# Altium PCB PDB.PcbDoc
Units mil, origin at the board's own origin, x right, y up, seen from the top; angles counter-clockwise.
Board outline 4440 x 3165 mil, 2 copper layers (Top Layer, Bottom Layer); 19 components, 6 nets, 44 pads, 729 vias.
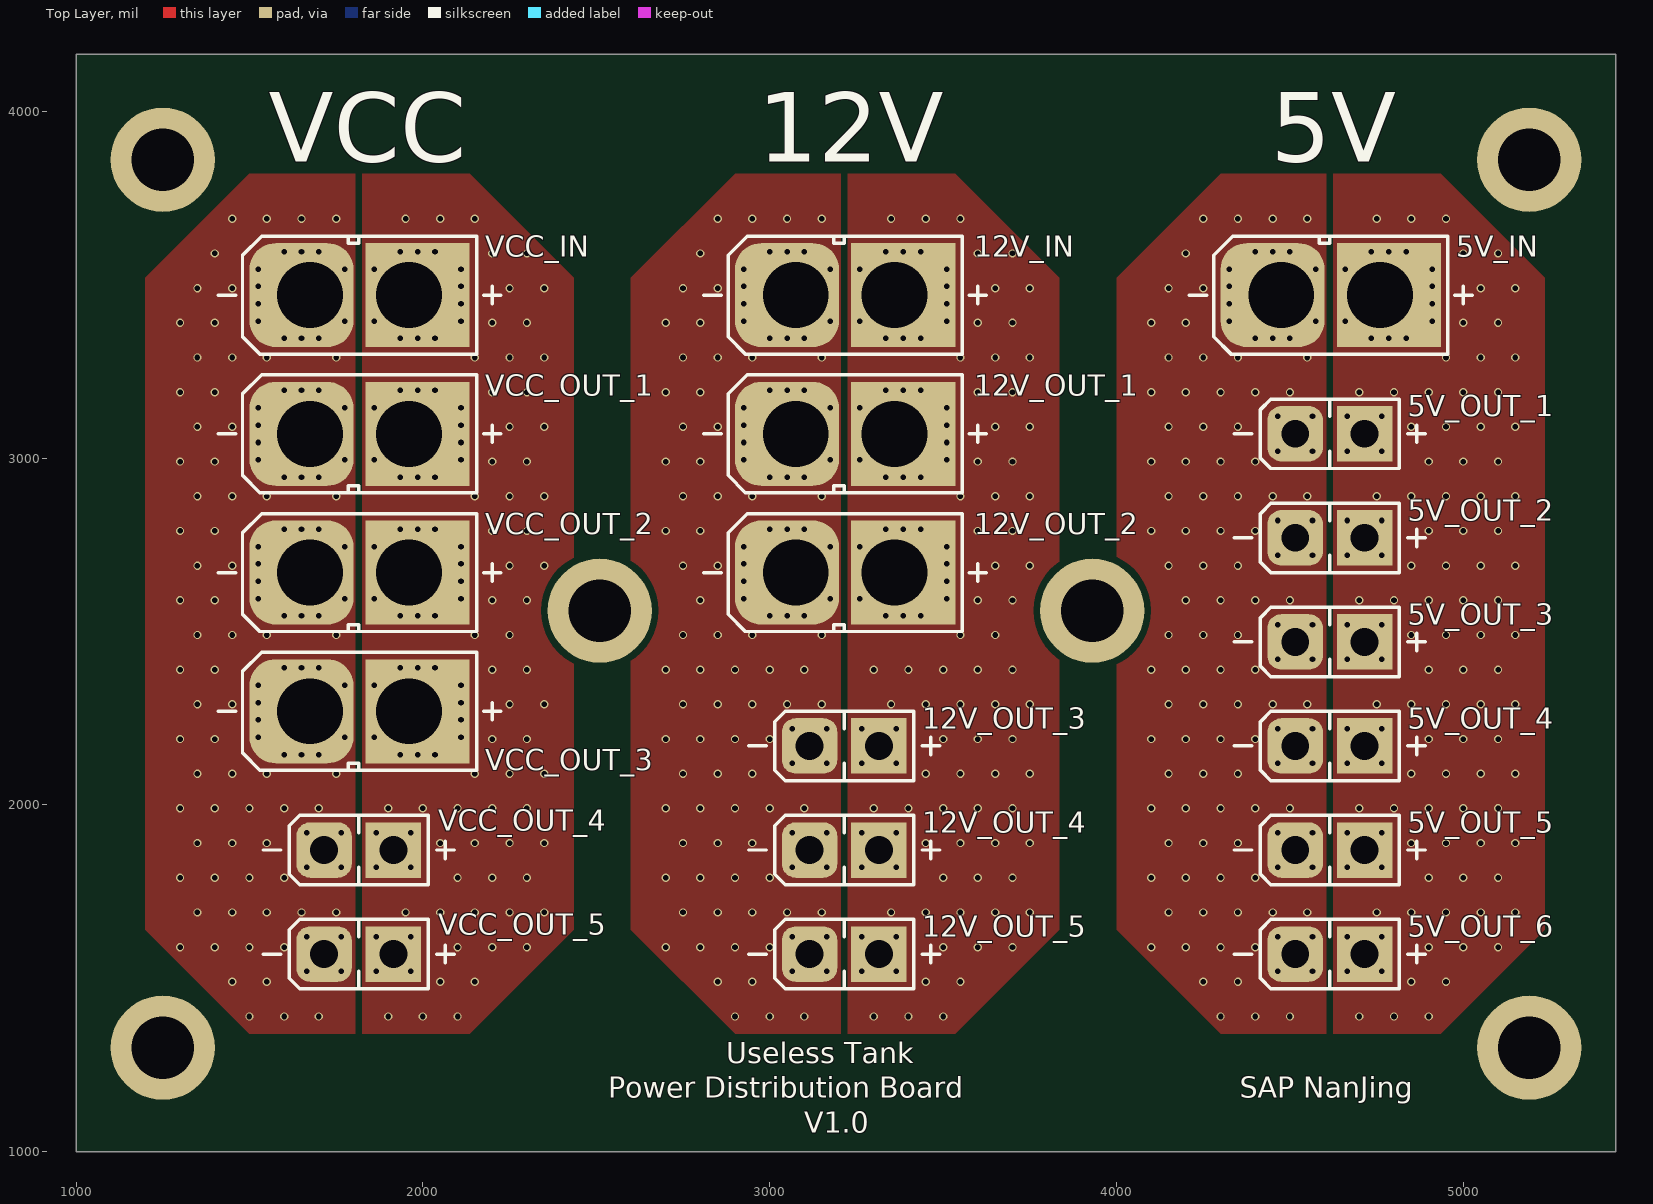
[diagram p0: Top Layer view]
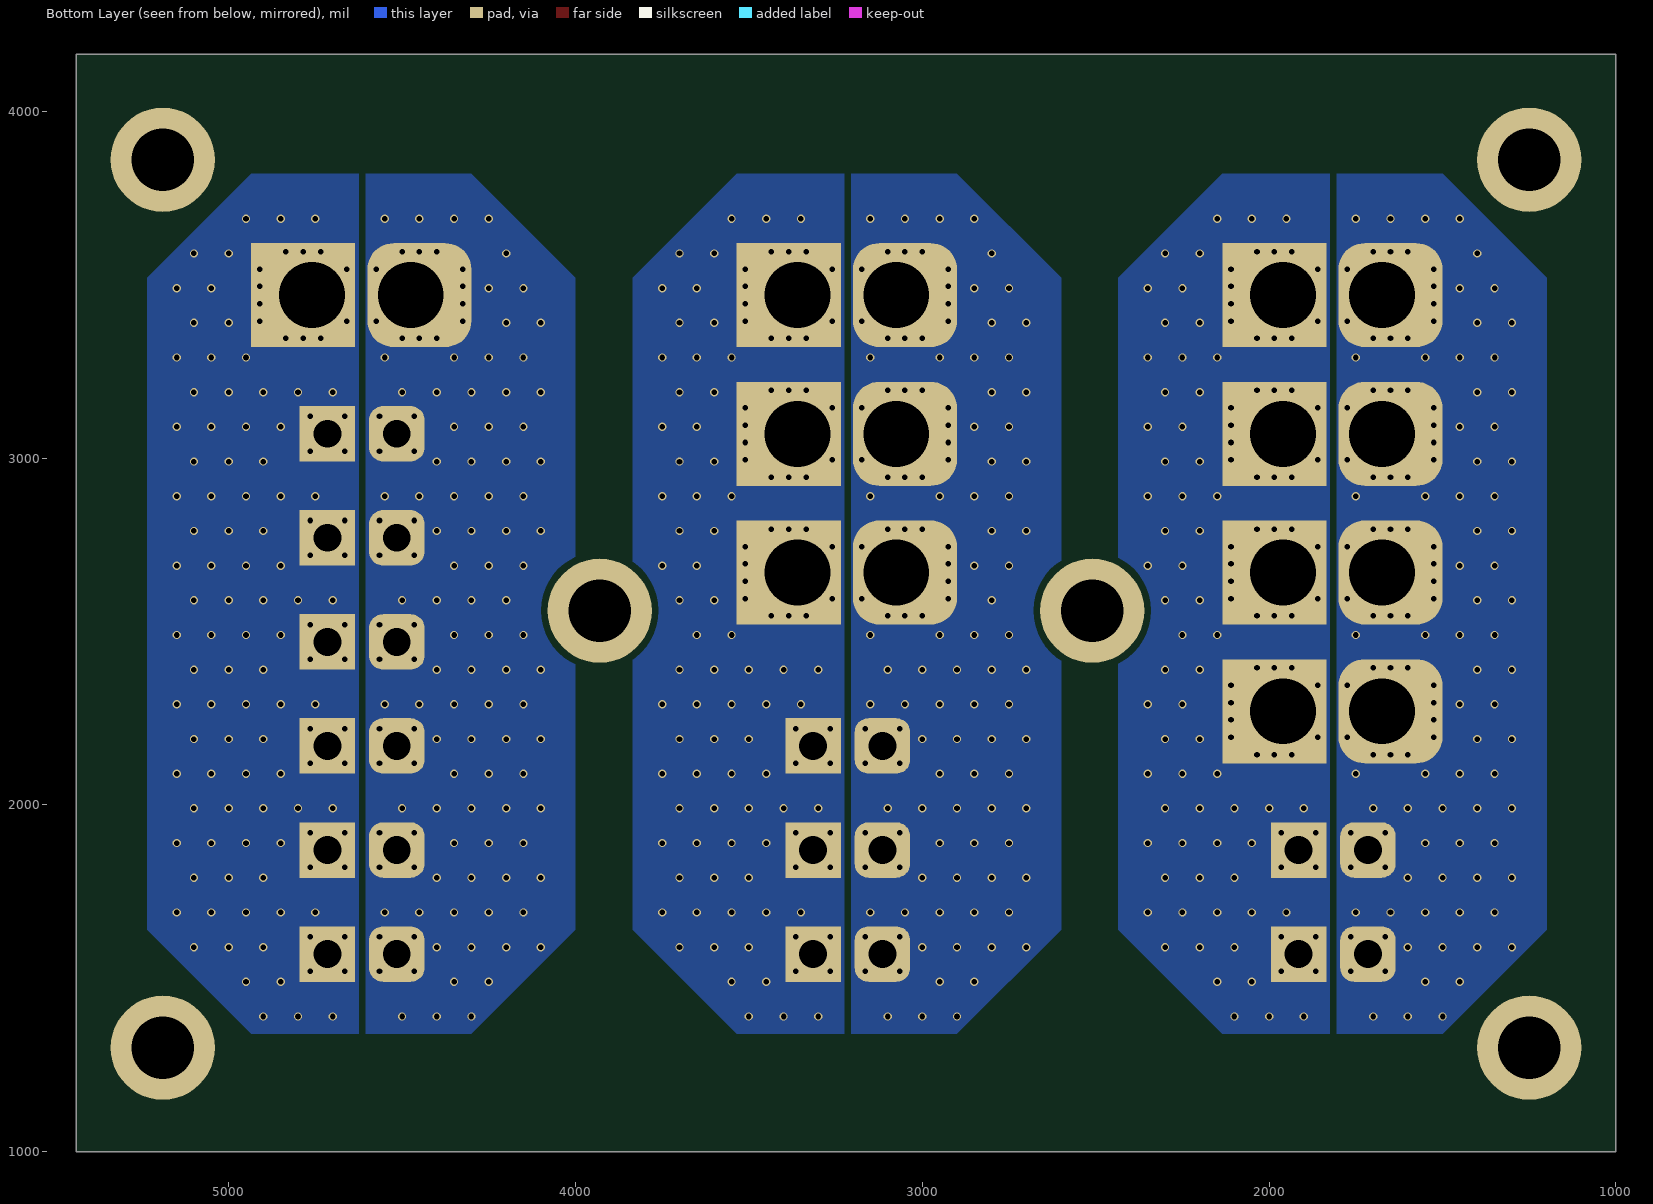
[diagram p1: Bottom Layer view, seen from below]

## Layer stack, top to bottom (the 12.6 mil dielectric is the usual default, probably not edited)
Top Solder: solder mask 0.4, Solder Resist, Dk 3.5
Top Layer: signal copper 1.4
Dielectric 1: dielectric 12.6, FR-4, Dk 4.8
Bottom Layer: signal copper 1.4
Bottom Solder: solder mask 0.4, Solder Resist, Dk 3.5

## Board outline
1000,1000 1000,4165 5440,4165 5440,1000

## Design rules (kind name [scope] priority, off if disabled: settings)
Clearance [All] p1: gap=20
HoleSize [All] p1: absolutevalues=TRUE maxlimit=200 minlimit=12 maxpercent=80.000 minpercent=20.000
PolygonConnect "Full Connect" [All] p1: connectstyle=Direct reliefconductorwidth=10 reliefentries=4 polygonreliefangle="90 Angle" airgapwidth=10
PolygonConnect [All] p2: connectstyle=Relief reliefconductorwidth=10 reliefentries=4 polygonreliefangle="90 Angle" airgapwidth=10
RoutingVias [All] p1: holewidth=16 width=24 viastyle="Through Hole" minholewidth=8 minwidth=14 maxholewidth=50 maxwidth=80
SolderMaskExpansion [All] p1: expansion=4
Width [All] p1: maxlimit=10 minlimit=8 preferedwidth=10
29 further rules are at their usual default settings.

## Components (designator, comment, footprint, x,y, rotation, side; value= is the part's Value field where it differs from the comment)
5V_IN "Header XT30/60/90" XT60PB-M 4475,3470 r0 top
5V_OUT_1 "Header XT30/60/90" XT30UPB-F 4515,3070 r0 top
5V_OUT_2 "Header XT30/60/90" XT30UPB-F 4515,2770 r0 top
5V_OUT_3 "Header XT30/60/90" XT30UPB-F 4515,2470 r0 top
5V_OUT_4 "Header XT30/60/90" XT30UPB-F 4515,2170 r0 top
5V_OUT_5 "Header XT30/60/90" XT30UPB-F 4515,1870 r0 top
5V_OUT_6 "Header XT30/60/90" XT30UPB-F 4515,1570 r0 top
12V_IN "Header XT30/60/90" XT60PB-M 3075,3470 r0 top
12V_OUT_1 "Header XT30/60/90" XT60PB-F 3075,3070 r0 top
12V_OUT_2 "Header XT30/60/90" XT60PB-F 3075,2670 r0 top
12V_OUT_3 "Header XT30/60/90" XT30UPB-F 3115,2170 r0 top
12V_OUT_4 "Header XT30/60/90" XT30UPB-F 3115,1870 r0 top
12V_OUT_5 "Header XT30/60/90" XT30UPB-F 3115,1570 r0 top
VCC_IN "Header XT30/60/90" XT60PB-M 1675,3470 r0 top
VCC_OUT_1 "Header XT30/60/90" XT60PB-F 1675,3070 r0 top
VCC_OUT_2 "Header XT30/60/90" XT60PB-F 1675,2670 r0 top
VCC_OUT_3 "Header XT30/60/90" XT60PB-F 1675,2270 r0 top
VCC_OUT_4 "Header XT30/60/90" XT30UPB-F 1715,1870 r0 top
VCC_OUT_5 "Header XT30/60/90" XT30UPB-F 1715,1570 r0 top

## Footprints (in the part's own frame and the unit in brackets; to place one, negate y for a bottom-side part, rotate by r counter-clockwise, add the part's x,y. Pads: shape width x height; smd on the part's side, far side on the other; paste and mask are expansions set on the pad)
XT30UPB-F [mil]
  rrect50% 160x160 hole 80: GND(0,0)
  rect 160x160 hole 80: VCC(200,0)
  silkscreen extent -175,-100 375,100
XT60PB-F [mil]
  rrect50% 300x300 hole 190 copper offset -25,0: GND(0,0)
  rect 300x300 hole 190 copper offset 25,0: VCC(285,0)
  silkscreen extent -265,-170 550,170
XT60PB-M [mil]
  rrect50% 300x300 hole 190 copper offset -25,0: GND(0,0)
  rect 300x300 hole 190 copper offset 25,0: VCC(285,0)
  silkscreen extent -265,-170 550,170

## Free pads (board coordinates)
  round 300 hole 180: ""(1250,1300) ""(1250,3860) ""(2510,2560) ""(3930,2560) ""(5190,1300) ""(5190,3860)

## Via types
v1: diameter 24, hole 16, Top Layer to Bottom Layer, tented both sides, 449 vias
v2: diameter 24, hole 16, Top Layer to Bottom Layer, 280 vias

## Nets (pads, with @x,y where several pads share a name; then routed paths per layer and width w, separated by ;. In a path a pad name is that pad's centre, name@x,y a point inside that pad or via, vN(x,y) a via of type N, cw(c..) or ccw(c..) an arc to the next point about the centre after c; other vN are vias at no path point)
Net5V_IN_GND: 5V_IN.GND 5V_OUT_1.GND 5V_OUT_2.GND 5V_OUT_3.GND 5V_OUT_4.GND 5V_OUT_5.GND 5V_OUT_6.GND
  other v1: 4300,1390 4400,1390 4500,1390 4250,1490 4350,1490 4100,1590 4200,1590 4300,1590 4400,1590 4150,1690 4250,1690 4350,1690 4450,1690 4550,1690 4100,1790 4200,1790 4300,1790 4400,1790 4150,1890 4250,1890 4350,1890 4100,1990 4200,1990 4300,1990 4400,1990 4500,1990 4150,2090 4250,2090 4350,2090 4100,2190 4200,2190 4300,2190 4400,2190 4150,2290 4250,2290 4350,2290 4450,2290 4550,2290 4100,2390 4200,2390 4300,2390 4400,2390 4150,2490 4250,2490 4350,2490 4200,2590 4300,2590 4400,2590 4500,2590 4150,2690 4250,2690 4350,2690 4100,2790 4200,2790 4300,2790 4400,2790 4150,2890 4250,2890 4350,2890 4450,2890 4550,2890 4100,2990 4200,2990 4300,2990 4400,2990 4150,3090 4250,3090 4350,3090 4100,3190 4200,3190 4300,3190 4400,3190 4500,3190 4150,3290 4250,3290 4350,3290 4550,3290 4100,3390 4200,3390 4150,3490 4250,3490 4200,3590 4250,3690 4350,3690 4450,3690 4550,3690
  other v2: 4465,1520 4565,1520 4465,1620 4565,1620 4465,1820 4565,1820 4465,1920 4565,1920 4465,2120 4565,2120 4465,2220 4565,2220 4465,2420 4565,2420 4465,2520 4565,2520 4465,2720 4565,2720 4465,2820 4565,2820 4465,3020 4565,3020 4465,3120 4565,3120 4400,3345 4450,3345 4500,3345 4325,3395 4575,3395 4325,3445 4325,3495 4325,3545 4575,3545 4400,3595 4450,3595 4500,3595
Net5V_IN_VCC: 5V_IN.VCC 5V_OUT_1.VCC 5V_OUT_2.VCC 5V_OUT_3.VCC 5V_OUT_4.VCC 5V_OUT_5.VCC 5V_OUT_6.VCC
  other v1: 4700,1390 4800,1390 4900,1390 4850,1490 4950,1490 4900,1590 5000,1590 5100,1590 4750,1690 4850,1690 4950,1690 5050,1690 5150,1690 4900,1790 5000,1790 5100,1790 4850,1890 4950,1890 5050,1890 5150,1890 4700,1990 4800,1990 4900,1990 5000,1990 5100,1990 4850,2090 4950,2090 5050,2090 5150,2090 4900,2190 5000,2190 5100,2190 4750,2290 4850,2290 4950,2290 5050,2290 5150,2290 4900,2390 5000,2390 5100,2390 4850,2490 4950,2490 5050,2490 5150,2490 4700,2590 4800,2590 4900,2590 5000,2590 5100,2590 4850,2690 4950,2690 5050,2690 5150,2690 4900,2790 5000,2790 5100,2790 4750,2890 4850,2890 4950,2890 5050,2890 5150,2890 4900,2990 5000,2990 5100,2990 4850,3090 4950,3090 5050,3090 5150,3090 4700,3190 4800,3190 4900,3190 5000,3190 5100,3190 4950,3290 5050,3290 5150,3290 5000,3390 5100,3390 5050,3490 5150,3490 5000,3590 5100,3590 4750,3690 4850,3690 4950,3690
  other v2: 4665,1520 4765,1520 4665,1620 4765,1620 4665,1820 4765,1820 4665,1920 4765,1920 4665,2120 4765,2120 4665,2220 4765,2220 4665,2420 4765,2420 4665,2520 4765,2520 4665,2720 4765,2720 4665,2820 4765,2820 4665,3020 4765,3020 4665,3120 4765,3120 4735,3345 4785,3345 4835,3345 4660,3395 4910,3395 4910,3445 4910,3495 4660,3545 4910,3545 4735,3595 4785,3595 4835,3595
Net12V_IN_GND: 12V_IN.GND 12V_OUT_1.GND 12V_OUT_2.GND 12V_OUT_3.GND 12V_OUT_4.GND 12V_OUT_5.GND
  other v1: 2900,1390 3000,1390 3100,1390 2850,1490 2950,1490 2700,1590 2800,1590 2900,1590 3000,1590 2750,1690 2850,1690 2950,1690 3050,1690 3150,1690 2700,1790 2800,1790 2900,1790 3000,1790 2750,1890 2850,1890 2950,1890 2700,1990 2800,1990 2900,1990 3000,1990 3100,1990 2750,2090 2850,2090 2950,2090 2700,2190 2800,2190 2900,2190 3000,2190 2750,2290 2850,2290 2950,2290 3050,2290 3150,2290 2700,2390 2800,2390 2900,2390 3000,2390 3100,2390 2750,2490 2850,2490 2950,2490 3150,2490 2800,2590 2750,2690 2850,2690 2700,2790 2800,2790 2750,2890 2850,2890 2950,2890 3150,2890 2700,2990 2800,2990 2750,3090 2850,3090 2700,3190 2800,3190 2750,3290 2850,3290 2950,3290 3150,3290 2700,3390 2800,3390 2750,3490 2850,3490 2800,3590 2850,3690 2950,3690 3050,3690 3150,3690
  other v2: 3065,1520 3165,1520 3065,1620 3165,1620 3065,1820 3165,1820 3065,1920 3165,1920 3065,2120 3165,2120 3065,2220 3165,2220 3000,2545 3050,2545 3100,2545 2925,2595 3175,2595 2925,2645 2925,2695 2925,2745 3175,2745 3000,2795 3050,2795 3100,2795 3000,2945 3050,2945 3100,2945 2925,2995 3175,2995 2925,3045 2925,3095 2925,3145 3175,3145 3000,3195 3050,3195 3100,3195 3000,3345 3050,3345 3100,3345 2925,3395 3175,3395 2925,3445 2925,3495 2925,3545 3175,3545 3000,3595 3050,3595 3100,3595
Net12V_IN_VCC: 12V_IN.VCC 12V_OUT_1.VCC 12V_OUT_2.VCC 12V_OUT_3.VCC 12V_OUT_4.VCC 12V_OUT_5.VCC
  other v1: 3300,1390 3400,1390 3500,1390 3450,1490 3550,1490 3500,1590 3600,1590 3700,1590 3350,1690 3450,1690 3550,1690 3650,1690 3750,1690 3500,1790 3600,1790 3700,1790 3450,1890 3550,1890 3650,1890 3750,1890 3300,1990 3400,1990 3500,1990 3600,1990 3700,1990 3450,2090 3550,2090 3650,2090 3750,2090 3500,2190 3600,2190 3700,2190 3350,2290 3450,2290 3550,2290 3650,2290 3750,2290 3300,2390 3400,2390 3500,2390 3600,2390 3700,2390 3550,2490 3650,2490 3600,2590 3700,2590 3650,2690 3750,2690 3600,2790 3700,2790 3550,2890 3650,2890 3750,2890 3600,2990 3700,2990 3650,3090 3750,3090 3600,3190 3700,3190 3550,3290 3650,3290 3750,3290 3600,3390 3700,3390 3650,3490 3750,3490 3600,3590 3700,3590 3350,3690 3450,3690 3550,3690
  other v2: 3265,1520 3365,1520 3265,1620 3365,1620 3265,1820 3365,1820 3265,1920 3365,1920 3265,2120 3365,2120 3265,2220 3365,2220 3335,2545 3385,2545 3435,2545 3260,2595 3510,2595 3510,2645 3510,2695 3260,2745 3510,2745 3335,2795 3385,2795 3435,2795 3335,2945 3385,2945 3435,2945 3260,2995 3510,2995 3510,3045 3510,3095 3260,3145 3510,3145 3335,3195 3385,3195 3435,3195 3335,3345 3385,3345 3435,3345 3260,3395 3510,3395 3510,3445 3510,3495 3260,3545 3510,3545 3335,3595 3385,3595 3435,3595
NetVCC_IN_GND: VCC_IN.GND VCC_OUT_1.GND VCC_OUT_2.GND VCC_OUT_3.GND VCC_OUT_4.GND VCC_OUT_5.GND
  other v1: 1500,1390 1600,1390 1700,1390 1450,1490 1550,1490 1300,1590 1400,1590 1500,1590 1600,1590 1350,1690 1450,1690 1550,1690 1650,1690 1750,1690 1300,1790 1400,1790 1500,1790 1600,1790 1350,1890 1450,1890 1550,1890 1300,1990 1400,1990 1500,1990 1600,1990 1700,1990 1350,2090 1450,2090 1550,2090 1750,2090 1300,2190 1400,2190 1350,2290 1450,2290 1300,2390 1400,2390 1350,2490 1450,2490 1550,2490 1750,2490 1300,2590 1400,2590 1350,2690 1450,2690 1300,2790 1400,2790 1350,2890 1450,2890 1550,2890 1750,2890 1300,2990 1400,2990 1350,3090 1450,3090 1300,3190 1400,3190 1350,3290 1450,3290 1550,3290 1750,3290 1300,3390 1400,3390 1350,3490 1450,3490 1400,3590 1450,3690 1550,3690 1650,3690 1750,3690
  other v2: 1665,1520 1765,1520 1665,1620 1765,1620 1665,1820 1765,1820 1665,1920 1765,1920 1600,2145 1650,2145 1700,2145 1525,2195 1775,2195 1525,2245 1525,2295 1525,2345 1775,2345 1600,2395 1650,2395 1700,2395 1600,2545 1650,2545 1700,2545 1525,2595 1775,2595 1525,2645 1525,2695 1525,2745 1775,2745 1600,2795 1650,2795 1700,2795 1600,2945 1650,2945 1700,2945 1525,2995 1775,2995 1525,3045 1525,3095 1525,3145 1775,3145 1600,3195 1650,3195 1700,3195 1600,3345 1650,3345 1700,3345 1525,3395 1775,3395 1525,3445 1525,3495 1525,3545 1775,3545 1600,3595 1650,3595 1700,3595
NetVCC_IN_VCC: VCC_IN.VCC VCC_OUT_1.VCC VCC_OUT_2.VCC VCC_OUT_3.VCC VCC_OUT_4.VCC VCC_OUT_5.VCC
  other v1: 1900,1390 2000,1390 2100,1390 2050,1490 2150,1490 2100,1590 2200,1590 2300,1590 1950,1690 2050,1690 2150,1690 2250,1690 2350,1690 2100,1790 2200,1790 2300,1790 2050,1890 2150,1890 2250,1890 2350,1890 1900,1990 2000,1990 2100,1990 2200,1990 2300,1990 2150,2090 2250,2090 2350,2090 2200,2190 2300,2190 2250,2290 2350,2290 2200,2390 2300,2390 2150,2490 2250,2490 2200,2590 2300,2590 2250,2690 2350,2690 2200,2790 2300,2790 2150,2890 2250,2890 2350,2890 2200,2990 2300,2990 2250,3090 2350,3090 2200,3190 2300,3190 2150,3290 2250,3290 2350,3290 2200,3390 2300,3390 2250,3490 2350,3490 2200,3590 2300,3590 1950,3690 2050,3690 2150,3690
  other v2: 1865,1520 1965,1520 1865,1620 1965,1620 1865,1820 1965,1820 1865,1920 1965,1920 1935,2145 1985,2145 2035,2145 1860,2195 2110,2195 2110,2245 2110,2295 1860,2345 2110,2345 1935,2395 1985,2395 2035,2395 1935,2545 1985,2545 2035,2545 1860,2595 2110,2595 2110,2645 2110,2695 1860,2745 2110,2745 1935,2795 1985,2795 2035,2795 1935,2945 1985,2945 2035,2945 1860,2995 2110,2995 2110,3045 2110,3095 1860,3145 2110,3145 1935,3195 1985,3195 2035,3195 1935,3345 1985,3345 2035,3345 1860,3395 2110,3395 2110,3445 2110,3495 1860,3545 2110,3545 1935,3595 1985,3595 2035,3595

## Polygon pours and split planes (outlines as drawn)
Net5V_IN_VCC on Top Layer "Top Layer-No Net" (solid, pour order 14): 5235,3520 4935,3820 4625,3820 4625,1340 4935,1340 5235,1640
Net5V_IN_GND on Top Layer "Top Layer-No Net" (solid, pour order 16): 4610,3820 4300,3820 4000,3520 4000,1640 4300,1340 4610,1340
Net12V_IN_VCC on Top Layer "Top Layer-No Net" (solid, pour order 18): 3835,3520 3535,3820 3225,3820 3225,1340 3535,1340 3835,1640
Net12V_IN_GND on Top Layer "Top Layer-No Net" (solid, pour order 20): 3210,3820 2900,3820 2600,3520 2600,1640 2900,1340 3210,1340
NetVCC_IN_VCC on Top Layer "Top Layer-No Net" (solid, pour order 22): 2435,3520 2135,3820 1825,3820 1825,1340 2135,1340 2435,1640
NetVCC_IN_GND on Top Layer "Top Layer-No Net" (solid, pour order 24): 1810,3820 1500,3820 1200,3520 1200,1640 1500,1340 1810,1340
Net12V_IN_GND on Bottom Layer "Bottom Layer-Net12V_IN_GND" (solid, pour order 19): 3210,3820 2900,3820 2600,3520 2600,1640 2900,1340 3210,1340
Net12V_IN_VCC on Bottom Layer "Bottom Layer-Net12V_IN_VCC" (solid, pour order 17): 3835,3520 3535,3820 3225,3820 3225,1340 3535,1340 3835,1640
Net5V_IN_GND on Bottom Layer "Bottom Layer-Net5V_IN_GND" (solid, pour order 15): 4610,3820 4300,3820 4000,3520 4000,1640 4300,1340 4610,1340
Net5V_IN_VCC on Bottom Layer "Bottom Layer-Net5V_IN_VCC" (solid, pour order 13): 5235,3520 4935,3820 4625,3820 4625,1340 4935,1340 5235,1640
NetVCC_IN_GND on Bottom Layer "Bottom Layer-NetVCC_IN_GND" (solid, pour order 23): 1810,3820 1500,3820 1200,3520 1200,1640 1500,1340 1810,1340
NetVCC_IN_VCC on Bottom Layer "Bottom Layer-NetVCC_IN_VCC" (solid, pour order 21): 2435,3520 2135,3820 1825,3820 1825,1340 2135,1340 2435,1640

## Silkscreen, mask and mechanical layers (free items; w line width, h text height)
Top Overlay:
  text "VCC" at 1555,3855 h200
  text "12V" at 2965,3855 h200
  text "5V" at 4445,3855 h200
  text "Useless Tank" at 2875,1255 h60
  text "Power Distribution Board" at 2535,1155 h60
  text "SAP NanJing" at 4355,1155 h60
  text "V1.0" at 3100,1055 h60
Mechanical 1:
  the board outline again, w10
Drill Drawing:
  circle w3.33: c5648.12,1380 r25
  lines w3.33: 5623.12,1255 5673.12,1255 5648.12,1205 5623.12,1255 ; 5623.12,1505 5648.12,1517.5 5673.12,1505 5660.62,1530 5673.12,1555 5648.12,1542.5 5623.12,1555 5635.62,1530 5623.12,1505 ; 5623.12,1667.5 5635.62,1667.5 5648.12,1655 5660.62,1667.5 5673.12,1667.5 5660.62,1680 5673.12,1692.5 5660.62,1692.5 5648.12,1705 5635.62,1692.5 5623.12,1692.5 5635.62,1680 5623.12,1667.5
  lines w15: 5555,1160 9433.97,1160 ; 5555,1760 9433.97,1760 ; 6105.88,1010 6105.88,1910 ; 6803.69,1010 6803.69,1910 ; 8149.29,1010 8149.29,1910 ; 8655.17,1010 8655.17,1910 ; 5555,1010 9433.97,1010 9433.97,1910 5555,1910 5555,1010
  text "Symbol" at 5645,1805 h72
  text "Hit Count" at 6150.88,1805 h72
  text "Finished Hole Size" at 6848.69,1805 h72
  text "Plated" at 8194.29,1805 h72
  text "Hole Type" at 8700.17,1805 h72
  text "6" at 6150.88,1655 h60
  text "180.00mil (4.572mm)" at 6848.69,1655 h60
  text "PTH" at 8194.29,1655 h60
  text "Round" at 8700.17,1655 h60
  text "16" at 6150.88,1505 h60
  text "190.00mil (4.826mm)" at 6848.69,1505 h60
  text "PTH" at 8194.29,1505 h60
  text "Round" at 8700.17,1505 h60
  text "22" at 6150.88,1355 h60
  text "80.00mil (2.032mm)" at 6848.69,1355 h60
  text "PTH" at 8194.29,1355 h60
  text "Round" at 8700.17,1355 h60
  text "729" at 6150.88,1205 h60
  text "16.00mil (0.406mm)" at 6848.69,1205 h60
  text "PTH" at 8194.29,1205 h60
  text "Round" at 8700.17,1205 h60
  text "773 Total" at 6150.88,1055 h60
